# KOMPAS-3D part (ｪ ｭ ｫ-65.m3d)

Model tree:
1. Эскиз:1
2. Операция выдавливания:1
     Расстояние 1 = 1
3. Эскиз:2
4. Операция выдавливания:2
     Расстояние 1 = 2
5. Эскиз:3
6. Вырезать элемент выдавливания:1
     Расстояние 1 = 200
7. Эскиз:4
8. Операция выдавливания:3
     Расстояние 1 = 5
9. Эскиз:5
10. Операция выдавливания:4
     Расстояние 1 = 1
11. Эскиз:6
12. Операция выдавливания:5
     Расстояние 1 = 9
13. Эскиз:7
14. Операция выдавливания:6
     Расстояние 1 = 9; Расстояние 2 = 200
15. Эскиз:8
16. Вырезать элемент выдавливания:2
     Расстояние 1 = 10
